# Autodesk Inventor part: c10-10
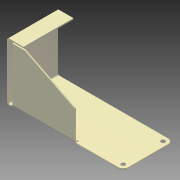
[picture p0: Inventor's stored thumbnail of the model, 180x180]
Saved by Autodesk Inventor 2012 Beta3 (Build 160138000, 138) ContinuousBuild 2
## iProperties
Created: 2011-01
Part Number: c10-10
Material: Steel, Mild
Document SubType Name: Sheet Metal
Designer: Beta-8540w
Density: 7.86 g/cm^3
Sheet Metal Rule: Steel - 16ga
Author: Beta-8540w
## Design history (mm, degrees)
sketch "Sketch1"
  geometry: L1 (-72.551, 64.215)-(-72.551, 124.215); L2 (-5.2, 64.215)-(-5.2, 124.215); L3 (0, 65.539)-(75, 65.539); L4 (133.476, 70.215)-(133.476, 118.215); L5 (76.524, 64.215)-(127.476, 64.215); L6 (0, 0)-(0, 67.263); L7 (75, 67.263)-(75, 30.34); L8 (75, 30.34)-(15, 0); L9 (15, 0)-(0, 0); L10 (-1.524, 67.263)-(-1.524, 64.215); L11 (76.524, 64.215)-(76.524, 67.263); L12 (-91.226, 64.215)-(-1.524, 64.215); L13 (127.476, 124.215)-(-91.226, 124.215); L14 (-91.226, 124.215)-(-91.226, 64.215); C1 r 2.553 at (127.476, 118.215); C2 r 2.553 at (127.476, 70.215); A1 r 6 centre (127.476, 118.215) between (133.476, 118.215) and (127.476, 124.215); A2 r 6 centre (127.476, 70.215) between (127.476, 64.215) and (133.476, 70.215); A3 r 0.762 centre (-0.762, 67.263) between (0, 67.263) and (-1.524, 67.263); A4 r 0.762 centre (75.762, 67.263) between (76.524, 67.263) and (75, 67.263); 10 further points
  constraints: 28 end point, 8 point on circle, 6 centre point, 6 point on line, 3 other
node "Face1"
feature "Fold1" dims "d1" = 1.524 (= BendReliefWidth), "d2" = 0.762 (= BendReliefDepth), "d3" = 3.048 (= MinimumRemnant), "d4" = 1.524 (= BendRadius), "d5" = 90 deg, "d6" = 1.524 (= BendRadius), "SeamGap" = 0.01, "Thickness" = 1.524 (derived)
feature "Fold2" dims "d7" = 1.524 (= BendReliefWidth), "d8" = 0.762 (= BendReliefDepth), "d9" = 3.048 (= MinimumRemnant), "d10" = 1.524 (= BendRadius), "d11" = 90 deg, "d12" = 1.524 (= BendRadius), "SeamGap" = 0.01, "Thickness" = 1.524 (derived)
feature "Fold3" dims "d13" = 1.524 (= BendReliefWidth), "d14" = 0.762 (= BendReliefDepth), "d15" = 3.048 (= MinimumRemnant), "d16" = 1.524 (= BendRadius), "d17" = 90 deg, "d18" = 1.524 (= BendRadius), "SeamGap" = 0.01, "Thickness" = 1.524 (derived)
body "Solid1"
face "Plate1" dims "Thickness" = 1.524 (derived)
other parameters: "BendRadius" = 1.524 (= Thickness), "BendReliefWidth" = 1.524 (= Thickness), "BendReliefDepth" = 0.762 (= 0.5 x Thickness), "CornerReliefSize" = 6.096 (= 4 x Thickness), "MinimumRemnant" = 3.048 (= 2 x Thickness), "TransitionRadius" = 1.524 (= BendRadius), "JacobiRadiusSize" = 1.524 (= BendRadius), "GapSize" = 0.762 (= 0.5 x Thickness), "d0" = 1.524 (= BendRadius)
